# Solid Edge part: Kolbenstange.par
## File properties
Username: ahadarics
Dokumentum tartalom típus: 0
Author: ahadarics
Last saved by: ahadarics
Revision: 84
Sűrűség: 0,000 kg/m^3
Pontosság: 0,990
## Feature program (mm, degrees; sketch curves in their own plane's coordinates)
base feature "unnamed BaseFeature 1"
thread "unnamed Thread 1"
chamfer "Letörés_1" setback 0.4
sketch for "Kihúzás_1" plane through (53.5, 0, 0) normal (1, 0, 0) x-axis (0, -1, 0)
  circle centre (0, 0) radius 8
extrude "Kihúzás_1" add finite 32 along -normal
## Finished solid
Body 1: solid body, 13 faces, 23 edges, 12 vertices.
  Faces by surface: plane 9, cylinder 3, cone 1
  Edges by curve: line 12, circle 11
Bounding box of the edges (mm): 330.500 x 16.000 x 16.000, from (-277, -8, -8) to (53.5, 8, 8).
Cylindrical faces by radius (mm): R3 x2, R8 x1
Conical faces (half-angle, radius in mm at the cone's reference point): 45 deg R2.6 x1
Planar faces by outward normal: +x 3, +z 1, -x 4, -z 1
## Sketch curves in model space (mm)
circle centre (53.5, 0, 0) radius 8
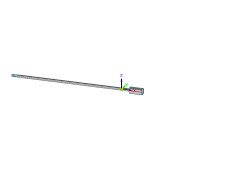
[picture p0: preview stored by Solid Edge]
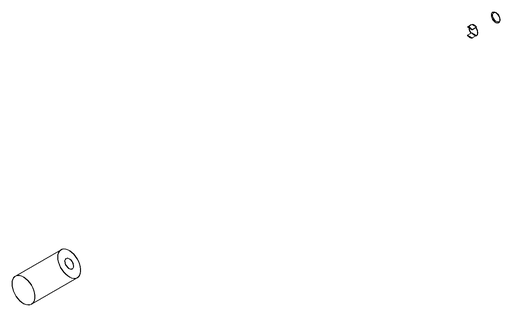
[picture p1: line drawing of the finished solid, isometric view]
